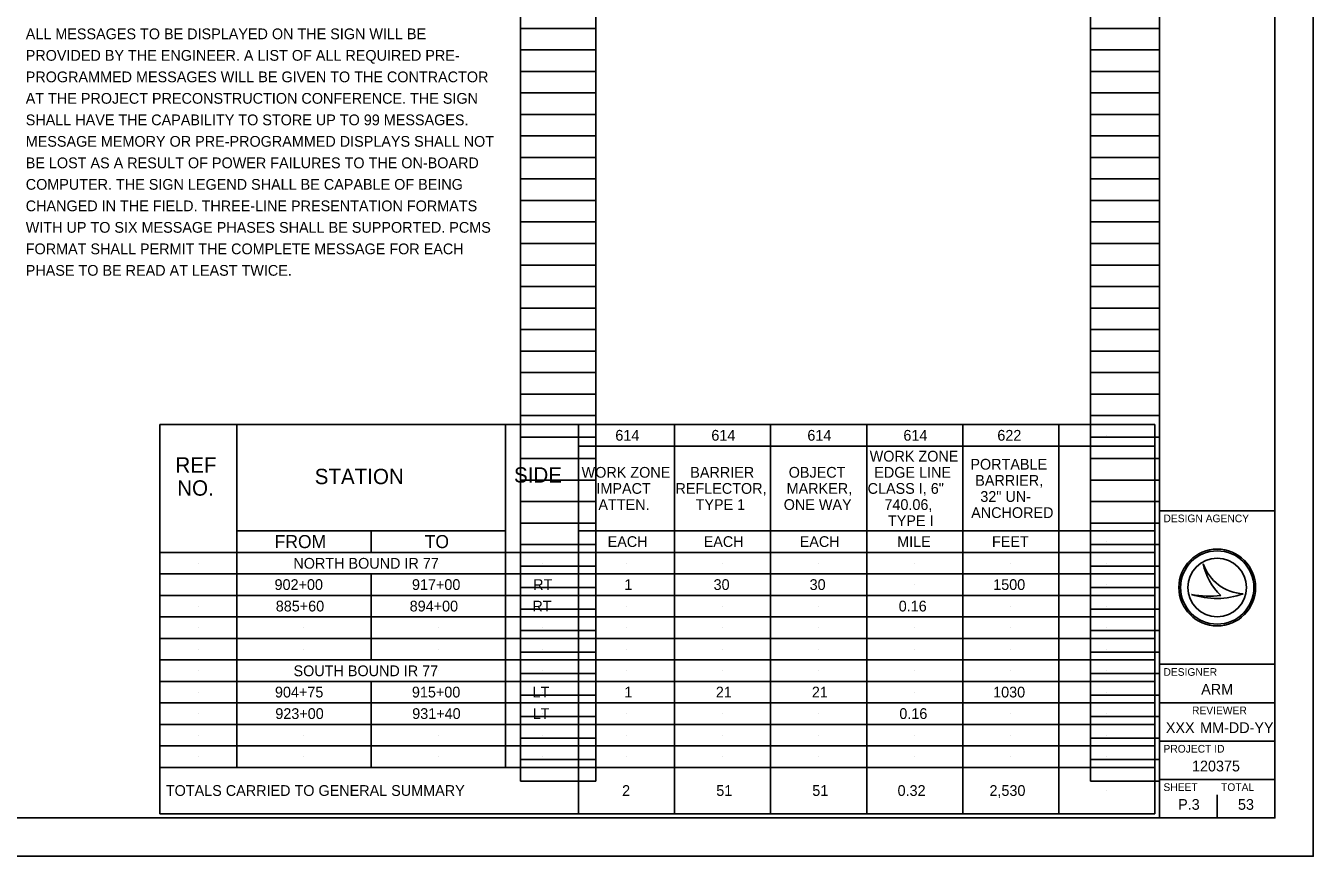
# Model space of a CAD drawing. Extents: x 0 to 34, y 0 to 22.
# Drawn here: x 17.24 to 34, y 0 to 10.82 of the extents above; entities that cross this region are included whole.
import ezdxf

# ---------------------------------------------------------------- set-up
doc = ezdxf.new("R2010")
doc.units = 0
for name, color, linetype in [('SH_Border', 7, 'Continuous'), ('SH_Cut_Line', 7, 'Continuous'), ('SH_Data', 7, 'Continuous'), ('SH_Text', 7, 'Continuous')]:
    doc.layers.add(name, color=color, linetype=linetype)

msp = doc.modelspace()

# ---------------------------------------------------------------- linework, layer by layer
at = {"layer": 'SH_Border'}
for p, q in [((32, 0.5), (32, 21.5)), ((32, 4.5), (33.5, 4.5)), ((32, 2.5), (33.5, 2.5)), ((32, 2), (33.5, 2)), ((32, 1.5), (33.5, 1.5)), ((32, 1), (33.5, 1))]:
    msp.add_line(p, q, dxfattribs=at)
msp.add_lwpolyline([(1.5, 21.5), (33.5, 21.5), (33.5, 0.5), (1.5, 0.5)], close=True, dxfattribs=at)
at = {"layer": 'SH_Cut_Line'}
msp.add_lwpolyline([(0, 0), (34, 0), (34, 22), (0, 22)], close=True, dxfattribs=at)
at = {"layer": 'SH_Data'}
for p, q in [((23.68, 0.98), (23.68, 21.14)), ((24.66, 0.98), (24.66, 21.14)), ((31.1, 0.98), (31.1, 21.14)), ((32, 0.98), (32, 21.14)), ((23.68, 10.78), (24.66, 10.78)), ((31.1, 10.78), (32, 10.78)), ((23.68, 10.5), (24.66, 10.5)), ((31.1, 10.5), (32, 10.5)), ((23.68, 10.22), (24.66, 10.22)), ((31.1, 10.22), (32, 10.22)), ((23.68, 9.94), (24.66, 9.94)), ((31.1, 9.94), (32, 9.94)), ((23.68, 9.66), (24.66, 9.66)), ((31.1, 9.66), (32, 9.66)), ((23.68, 9.38), (24.66, 9.38)), ((31.1, 9.38), (32, 9.38)), ((23.68, 9.1), (24.66, 9.1)), ((31.1, 9.1), (32, 9.1)), ((23.68, 8.82), (24.66, 8.82)), ((31.1, 8.82), (32, 8.82)), ((23.68, 8.54), (24.66, 8.54)), ((31.1, 8.54), (32, 8.54)), ((23.68, 8.26), (24.66, 8.26)), ((31.1, 8.26), (32, 8.26)), ((23.68, 7.98), (24.66, 7.98)), ((31.1, 7.98), (32, 7.98)), ((23.68, 7.7), (24.66, 7.7)), ((31.1, 7.7), (32, 7.7)), ((23.68, 7.42), (24.66, 7.42)), ((31.1, 7.42), (32, 7.42)), ((23.68, 7.14), (24.66, 7.14)), ((31.1, 7.14), (32, 7.14)), ((23.68, 6.86), (24.66, 6.86)), ((31.1, 6.86), (32, 6.86)), ((23.68, 6.58), (24.66, 6.58)), ((31.1, 6.58), (32, 6.58)), ((23.68, 6.3), (24.66, 6.3)), ((31.1, 6.3), (32, 6.3)), ((23.68, 6.02), (24.66, 6.02)), ((31.1, 6.02), (32, 6.02)), ((23.68, 5.74), (24.66, 5.74)), ((31.1, 5.74), (32, 5.74)), ((31.937, 5.622), (18.986, 5.622)), ((18.986, 5.622), (18.986, 0.554)), ((19.986, 5.622), (19.986, 1.158)), ((23.486, 5.622), (23.486, 1.158)), ((24.437, 0.554), (24.437, 5.622)), ((25.687, 0.554), (25.687, 5.622)), ((26.937, 0.554), (26.937, 5.622)), ((28.187, 0.554), (28.187, 5.622)), ((29.437, 0.554), (29.437, 5.622)), ((30.687, 0.554), (30.687, 5.622)), ((31.937, 1.158), (31.937, 5.622)), ((31.937, 0.554), (31.937, 5.622)), ((23.68, 5.46), (24.66, 5.46)), ((25.062, 5.482), (25.062, 5.482)), ((25.062, 5.482), (25.062, 5.482)), ((26.312, 5.482), (26.312, 5.482)), ((26.312, 5.482), (26.312, 5.482)), ((27.562, 5.482), (27.562, 5.482)), ((27.562, 5.482), (27.562, 5.482)), ((28.812, 5.482), (28.812, 5.482)), ((28.812, 5.482), (28.812, 5.482)), ((30.062, 5.482), (30.062, 5.482)), ((30.062, 5.482), (30.062, 5.482)), ((31.1, 5.46), (32, 5.46)), ((31.312, 5.482), (31.312, 5.482)), ((31.312, 5.482), (31.312, 5.482)), ((31.937, 5.342), (24.437, 5.342)), ((31.937, 5.342), (24.437, 5.342)), ((23.68, 5.18), (24.66, 5.18)), ((31.1, 5.18), (32, 5.18)), ((23.68, 4.9), (24.66, 4.9)), ((31.1, 4.9), (32, 4.9)), ((23.68, 4.62), (24.66, 4.62)), ((31.1, 4.62), (32, 4.62)), ((23.486, 4.238), (19.986, 4.238)), ((21.736, 4.238), (21.736, 3.958)), ((23.68, 4.34), (24.66, 4.34)), ((31.937, 4.238), (24.437, 4.238)), ((31.1, 4.34), (32, 4.34)), ((23.68, 4.06), (24.66, 4.06)), ((25.062, 4.098), (25.062, 4.098)), ((26.312, 4.098), (26.312, 4.098)), ((27.562, 4.098), (27.562, 4.098)), ((28.812, 4.098), (28.812, 4.098)), ((30.062, 4.098), (30.062, 4.098)), ((31.1, 4.06), (32, 4.06)), ((31.312, 4.098), (31.312, 4.098)), ((31.937, 3.958), (18.986, 3.958)), ((19.486, 3.818), (19.486, 3.818)), ((20.861, 3.818), (20.861, 3.818)), ((22.611, 3.818), (22.611, 3.818)), ((23.68, 3.78), (24.66, 3.78)), ((23.961, 3.818), (23.961, 3.818)), ((25.062, 3.818), (25.062, 3.818)), ((26.312, 3.818), (26.312, 3.818)), ((27.562, 3.818), (27.562, 3.818)), ((28.812, 3.818), (28.812, 3.818)), ((30.062, 3.818), (30.062, 3.818)), ((31.1, 3.78), (32, 3.78)), ((31.312, 3.818), (31.312, 3.818)), ((32.567, 3.81), (32.567, 3.81)), ((31.937, 3.678), (18.986, 3.678)), ((20.861, 3.538), (20.861, 3.538)), ((21.736, 3.678), (21.736, 2.558)), ((22.611, 3.538), (22.611, 3.538)), ((23.961, 3.538), (23.961, 3.538)), ((25.062, 3.538), (25.062, 3.538)), ((26.312, 3.538), (26.312, 3.538)), ((27.562, 3.538), (27.562, 3.538)), ((28.812, 3.538), (28.812, 3.538)), ((30.062, 3.538), (30.062, 3.538)), ((31.312, 3.538), (31.312, 3.538)), ((31.937, 3.398), (18.986, 3.398)), ((23.68, 3.5), (24.66, 3.5)), ((31.1, 3.5), (32, 3.5)), ((32.417, 3.41), (32.417, 3.41)), ((32.75, 3.5), (32.75, 3.5)), ((33.087, 3.419), (33.087, 3.419)), ((19.486, 3.258), (19.486, 3.258)), ((20.861, 3.258), (20.861, 3.258)), ((22.611, 3.258), (22.611, 3.258)), ((23.68, 3.22), (24.66, 3.22)), ((23.961, 3.258), (23.961, 3.258)), ((25.062, 3.258), (25.062, 3.258)), ((26.312, 3.258), (26.312, 3.258)), ((27.562, 3.258), (27.562, 3.258)), ((28.812, 3.258), (28.812, 3.258)), ((30.062, 3.258), (30.062, 3.258)), ((31.1, 3.22), (32, 3.22)), ((31.312, 3.258), (31.312, 3.258)), ((31.937, 3.118), (18.986, 3.118)), ((19.486, 2.978), (19.486, 2.978)), ((20.861, 2.978), (20.861, 2.978)), ((22.611, 2.978), (22.611, 2.978)), ((23.68, 2.94), (24.66, 2.94)), ((23.961, 2.978), (23.961, 2.978)), ((25.062, 2.978), (25.062, 2.978)), ((26.312, 2.978), (26.312, 2.978)), ((27.562, 2.978), (27.562, 2.978)), ((28.812, 2.978), (28.812, 2.978)), ((30.062, 2.978), (30.062, 2.978)), ((31.1, 2.94), (32, 2.94)), ((31.312, 2.978), (31.312, 2.978)), ((31.937, 2.838), (18.986, 2.838)), ((19.486, 2.698), (19.486, 2.698)), ((20.861, 2.698), (20.861, 2.698)), ((22.611, 2.698), (22.611, 2.698)), ((23.961, 2.698), (23.961, 2.698)), ((25.062, 2.698), (25.062, 2.698)), ((26.312, 2.698), (26.312, 2.698)), ((27.562, 2.698), (27.562, 2.698)), ((28.812, 2.698), (28.812, 2.698)), ((30.062, 2.698), (30.062, 2.698)), ((31.312, 2.698), (31.312, 2.698)), ((31.937, 2.558), (18.986, 2.558)), ((23.68, 2.66), (24.66, 2.66)), ((31.1, 2.66), (32, 2.66)), ((19.486, 2.418), (19.486, 2.418)), ((20.861, 2.418), (20.861, 2.418)), ((22.611, 2.418), (22.611, 2.418)), ((23.68, 2.38), (24.66, 2.38)), ((23.961, 2.418), (23.961, 2.418)), ((25.062, 2.418), (25.062, 2.418)), ((26.312, 2.418), (26.312, 2.418)), ((27.562, 2.418), (27.562, 2.418)), ((28.812, 2.418), (28.812, 2.418)), ((30.062, 2.418), (30.062, 2.418)), ((31.1, 2.38), (32, 2.38)), ((31.312, 2.418), (31.312, 2.418)), ((31.937, 2.278), (18.986, 2.278)), ((21.736, 2.278), (21.736, 1.158)), ((19.486, 2.138), (19.486, 2.138)), ((20.861, 2.138), (20.861, 2.138)), ((22.611, 2.138), (22.611, 2.138)), ((23.68, 2.1), (24.66, 2.1)), ((23.961, 2.138), (23.961, 2.138)), ((25.062, 2.138), (25.062, 2.138)), ((26.312, 2.138), (26.312, 2.138)), ((27.562, 2.138), (27.562, 2.138)), ((28.812, 2.138), (28.812, 2.138)), ((30.062, 2.138), (30.062, 2.138)), ((31.1, 2.1), (32, 2.1)), ((31.312, 2.138), (31.312, 2.138)), ((31.937, 1.998), (18.986, 1.998)), ((19.486, 1.858), (19.486, 1.858)), ((20.861, 1.858), (20.861, 1.858)), ((22.611, 1.858), (22.611, 1.858)), ((23.961, 1.858), (23.961, 1.858)), ((25.062, 1.858), (25.062, 1.858)), ((26.312, 1.858), (26.312, 1.858)), ((27.562, 1.858), (27.562, 1.858)), ((28.812, 1.858), (28.812, 1.858)), ((30.062, 1.858), (30.062, 1.858)), ((31.312, 1.858), (31.312, 1.858)), ((31.937, 1.718), (18.986, 1.718)), ((23.68, 1.82), (24.66, 1.82)), ((31.1, 1.82), (32, 1.82)), ((19.486, 1.578), (19.486, 1.578)), ((20.861, 1.578), (20.861, 1.578)), ((22.611, 1.578), (22.611, 1.578)), ((23.68, 1.54), (24.66, 1.54)), ((23.961, 1.578), (23.961, 1.578)), ((25.062, 1.578), (25.062, 1.578)), ((26.312, 1.578), (26.312, 1.578)), ((27.562, 1.578), (27.562, 1.578)), ((28.812, 1.578), (28.812, 1.578)), ((30.062, 1.578), (30.062, 1.578)), ((31.1, 1.54), (32, 1.54)), ((31.312, 1.578), (31.312, 1.578)), ((31.937, 1.438), (18.986, 1.438)), ((19.486, 1.298), (19.486, 1.298)), ((20.861, 1.298), (20.861, 1.298)), ((22.611, 1.298), (22.611, 1.298)), ((23.68, 1.26), (24.66, 1.26)), ((23.961, 1.298), (23.961, 1.298)), ((25.062, 1.298), (25.062, 1.298)), ((26.312, 1.298), (26.312, 1.298)), ((27.562, 1.298), (27.562, 1.298)), ((28.812, 1.298), (28.812, 1.298)), ((30.062, 1.298), (30.062, 1.298)), ((31.1, 1.26), (32, 1.26)), ((31.312, 1.298), (31.312, 1.298)), ((31.937, 1.158), (18.986, 1.158)), ((31.937, 1.158), (18.986, 1.158)), ((23.68, 0.98), (24.66, 0.98)), ((25.062, 0.856), (25.062, 0.856)), ((26.312, 0.856), (26.312, 0.856)), ((27.562, 0.856), (27.562, 0.856)), ((28.812, 0.856), (28.812, 0.856)), ((30.062, 0.856), (30.062, 0.856)), ((31.1, 0.98), (32, 0.98)), ((31.312, 0.856), (31.312, 0.856)), ((32.375, 0.675), (32.375, 0.675)), ((32.75, 0.5), (32.75, 0.8)), ((31.937, 0.554), (18.986, 0.554))]:
    msp.add_line(p, q, dxfattribs=at)
for radius in [0.5, 0.477, 0.477, 0.382]:
    msp.add_circle((32.75, 3.5), radius, dxfattribs=at)
for centre, radius, start, end in [((33.116, 3.998), 0.58, 198.9257, 198.9319), ((33.347, 3.97), 0.796, 191.6379, 191.6421), ((33.116, 3.998), 0.58, 198.9319, 267.1657), ((33.347, 3.97), 0.796, 191.6421, 226.0947), ((32.739, 4.37), 1.013, 251.4576, 290.0832), ((32.648, 4.654), 1.266, 259.4964, 259.4995), ((32.739, 4.37), 1.013, 251.4527, 251.4576), ((32.648, 4.654), 1.266, 259.4995, 276.6672)]:
    msp.add_arc(centre, radius, start, end, dxfattribs=at)

# ---------------------------------------------------------------- texts
for s, height, p in [('REF', 0.2, (19.189, 4.996)), ('STATION', 0.2, (21.002, 4.846)), ('SIDE', 0.2, (23.596, 4.866)), ('NO.', 0.2, (19.212, 4.696)), ('FROM', 0.17, (20.481, 4.013)), ('TO', 0.17, (22.434, 4.013)), ('TOTALS CARRIED TO GENERAL SUMMARY', 0.14, (19.064, 0.786))]:
    msp.add_text(s, height=height, rotation=360, dxfattribs=at).set_placement(p)
for s, height, p in [('DESIGN AGENCY', 0.1, (32.05, 4.35)), ('DESIGNER', 0.1, (32.05, 2.35)), ('ARM', 0.14, (32.541, 2.105)), ('REVIEWER', 0.1, (32.422, 1.85)), ('XXX', 0.14, (32.081, 1.605)), ('MM-DD-YY', 0.14, (32.527, 1.605)), ('PROJECT ID', 0.1, (32.05, 1.35)), ('120375', 0.14, (32.421, 1.105)), ('SHEET', 0.1, (32.05, 0.85)), ('TOTAL', 0.1, (32.8, 0.85)), ('P.3', 0.14, (32.241, 0.605)), ('53', 0.14, (33.02, 0.605))]:
    msp.add_text(s, height=height, dxfattribs=at).set_placement(p)
at = {"layer": 'SH_Text'}
for s, p in [('ALL MESSAGES TO BE DISPLAYED ON THE SIGN WILL BE', (17.24, 10.64)), ('PROVIDED BY THE ENGINEER. A LIST OF ALL REQUIRED PRE-', (17.24, 10.36)), ('PROGRAMMED MESSAGES WILL BE GIVEN TO THE CONTRACTOR', (17.24, 10.08)), ('AT THE PROJECT PRECONSTRUCTION CONFERENCE. THE SIGN', (17.24, 9.8)), ('SHALL HAVE THE CAPABILITY TO STORE UP TO 99 MESSAGES.', (17.24, 9.52)), ('MESSAGE MEMORY OR PRE-PROGRAMMED DISPLAYS SHALL NOT', (17.24, 9.24)), ('BE LOST AS A RESULT OF POWER FAILURES TO THE ON-BOARD', (17.24, 8.96)), ('COMPUTER. THE SIGN LEGEND SHALL BE CAPABLE OF BEING', (17.24, 8.68)), ('CHANGED IN THE FIELD. THREE-LINE PRESENTATION FORMATS', (17.24, 8.4)), ('WITH UP TO SIX MESSAGE PHASES SHALL BE SUPPORTED. PCMS', (17.24, 8.12)), ('FORMAT SHALL PERMIT THE COMPLETE MESSAGE FOR EACH', (17.24, 7.84)), ('PHASE TO BE READ AT LEAST TWICE.', (17.24, 7.56)), ('NORTH BOUND IR 77', (20.724, 3.745)), ('902+00', (20.479, 3.468)), ('917+00', (22.268, 3.468)), ('RT', (23.845, 3.468)), ('1', (25.032, 3.468)), ('30', (26.194, 3.468)), ('30', (27.444, 3.468)), ('1500', (29.834, 3.468)), ('885+60', (20.495, 3.188)), ('894+00', (22.238, 3.188)), ('RT', (23.835, 3.188)), ('0.16', (28.604, 3.188)), ('SOUTH BOUND IR 77', (20.726, 2.345)), ('904+75', (20.484, 2.068)), ('915+00', (22.267, 2.068)), ('LT', (23.838, 2.068)), ('1', (25.032, 2.068)), ('21', (26.223, 2.068)), ('21', (27.473, 2.068)), ('1030', (29.833, 2.068)), ('923+00', (20.489, 1.788)), ('931+40', (22.271, 1.788)), ('LT', (23.839, 1.788)), ('0.16', (28.612, 1.788)), ('2', (25.003, 0.786)), ('51', (26.229, 0.786)), ('51', (27.479, 0.786)), ('0.32', (28.589, 0.786)), ('2,530', (29.785, 0.786))]:
    msp.add_text(s, height=0.14, dxfattribs=at).set_placement(p)
for s, p in [('614', (24.915, 5.412)), ('614', (26.165, 5.412)), ('614', (27.415, 5.412)), ('614', (28.665, 5.412)), ('622', (29.888, 5.412)), ('WORK ZONE', (28.226, 5.14)), ('WORK ZONE', (24.476, 4.93)), ('BARRIER', (25.891, 4.93)), ('OBJECT', (27.172, 4.93)), ('EDGE LINE', (28.286, 4.93)), ('PORTABLE', (29.537, 5.035)), ('IMPACT', (24.669, 4.72)), ('REFLECTOR,', (25.698, 4.72)), ('CLASS I, 6"', (28.199, 4.72)), ('BARRIER, ', (29.6, 4.825)), ('MARKER,', (27.145, 4.72)), ('32" UN-', (29.666, 4.615)), ('ATTEN.', (24.695, 4.51)), ('TYPE 1', (25.96, 4.51)), ('ONE WAY', (27.107, 4.51)), ('740.06,', (28.418, 4.51)), ('ANCHORED', (29.547, 4.405)), ('TYPE I', (28.464, 4.3)), ('EACH', (24.815, 4.028)), ('EACH', (26.065, 4.028)), ('EACH', (27.315, 4.028)), ('MILE', (28.584, 4.028)), ('FEET', (29.818, 4.028))]:
    msp.add_text(s, height=0.14, rotation=360, dxfattribs=at).set_placement(p)

doc.saveas('drawing.dxf')
